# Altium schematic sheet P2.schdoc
size 297 x 210 mm; Symbol: Sheet-Symbol_A4; Company: 嘉立创EDA; Version: V1.0; Page Size: A4; @Project Name: MYNOVA-射频遥控; @Page Count: 2; @Update Date: 2025-11-18; @Create Date: 2025-11-18; @Schematic Name: 双频射频遥控V2; @Page No: 2; @Page Name: P2; Device: Sheet-Symbol_A4
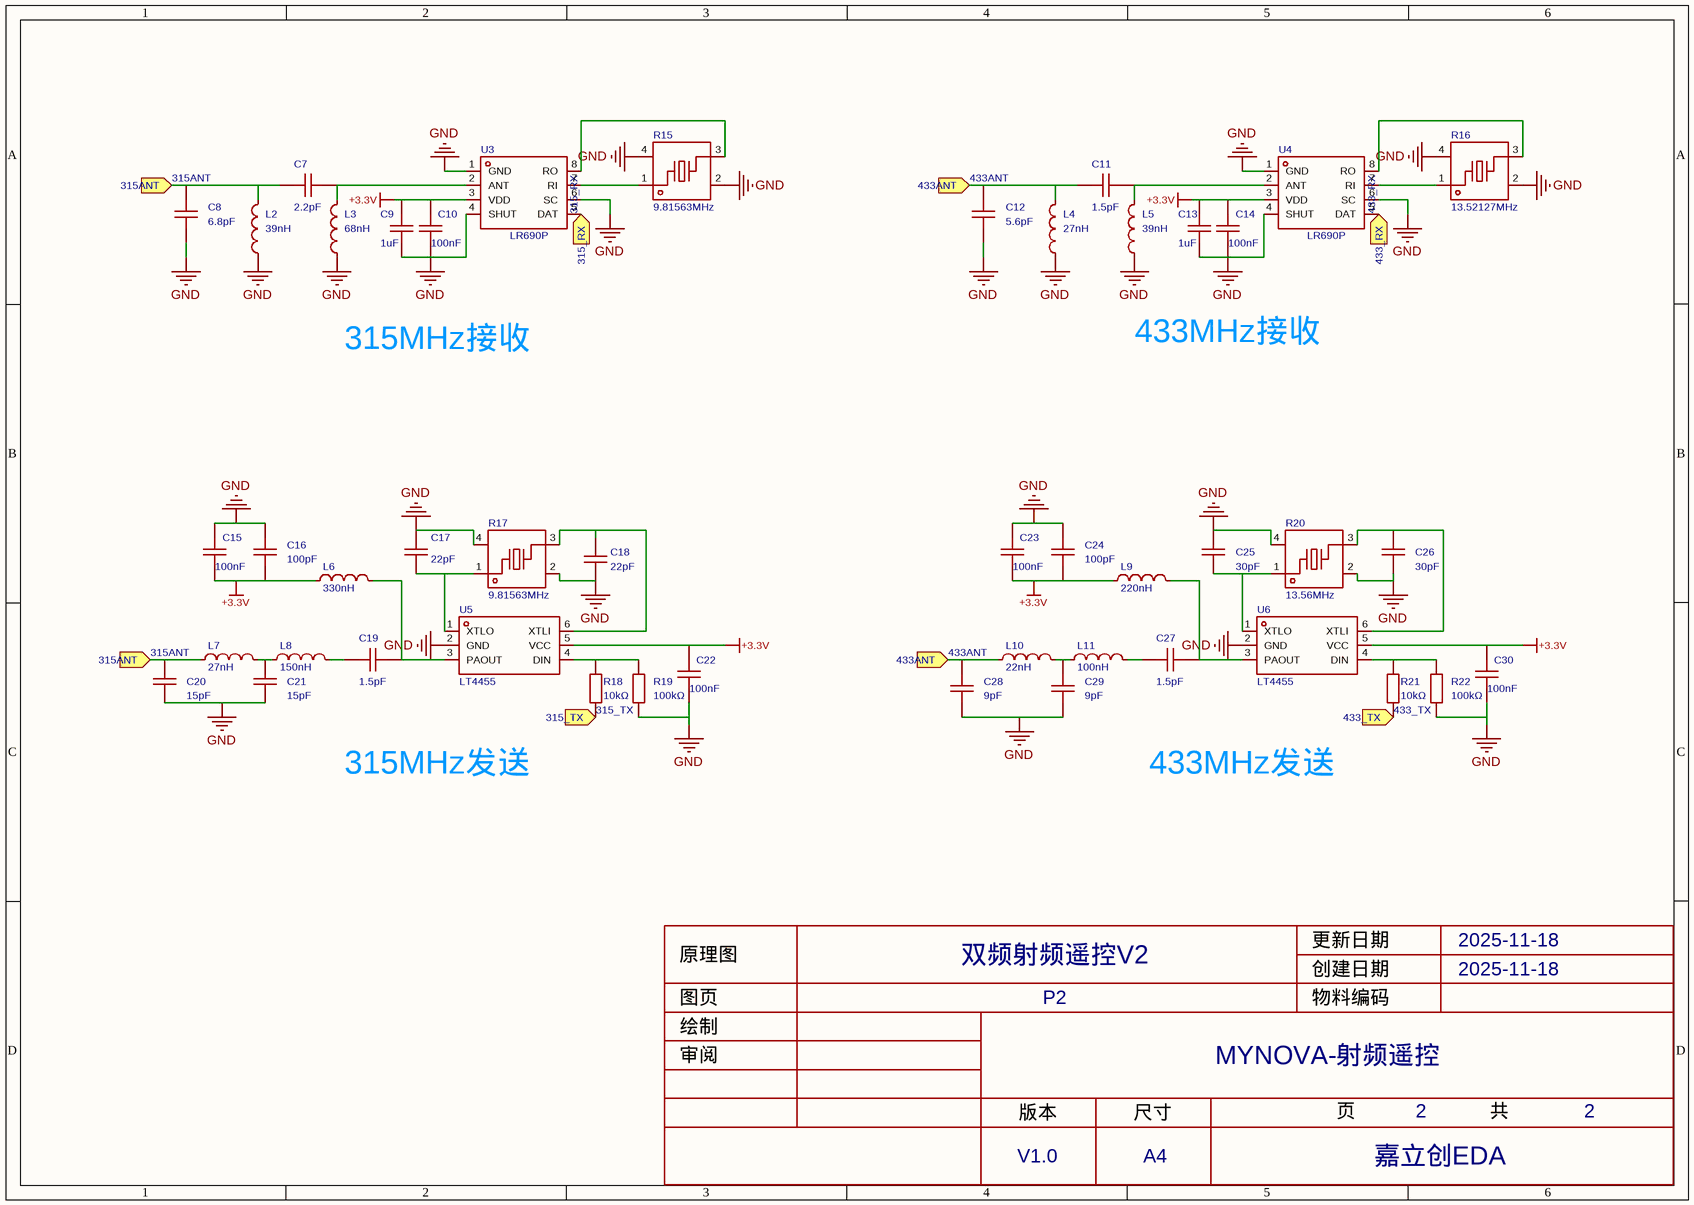
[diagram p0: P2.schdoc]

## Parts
C7  2.2pF  [C0603]
C8  6.8pF  [C0603]
C9  1uF  [C0603]
C10  100nF  [C0603]
C11  1.5pF  [C0603]
C12  5.6pF  [C0603]
C13  1uF  [C0603]
C14  100nF  [C0603]
C15  100nF  [C0603]
C16  100pF  [C0603]
C17  22pF  [C0603]
C18  22pF  [C0603]
C19  1.5pF  [C0603]
C20  15pF  [C0603]
C21  15pF  [C0603]
C22  100nF  [C0603]
C23  100nF  [C0603]
C24  100pF  [C0603]
C25  30pF  [C0603]
C26  30pF  [C0603]
C27  1.5pF  [C0603]
C28  9pF  [C0603]
C29  9pF  [C0603]
C30  100nF  [C0603]
L2  39nH  [L0603]
L3  68nH  [L0603]
L4  27nH  [L0603]
L5  39nH  [L0603]
L6  330nH  [L0603]
L7  27nH  [L0603]
L8  150nH  [IND-SMD_L1.8-W1.1]
L9  220nH  [L0603]
L10  22nH  [L0603]
L11  100nH  [L0603]
R15  9.81563MHz  [CRYSTAL-SMD_4P-L3.2-W2.5-BL]
R16  13.52127MHz  [CRYSTAL-SMD_4P-L3.2-W2.5-BL]
R17  9.81563MHz  [CRYSTAL-SMD_4P-L3.2-W2.5-BL]
R18  10kΩ  [R0603]
R19  100kΩ  [R0603]
R20  13.56MHz  [CRYSTAL-SMD_4P-L3.2-W2.5-BL_SIT8008BI]
R21  10kΩ  [R0603]
R22  100kΩ  [R0603]
U3  LR690P  [SOP-8_L4.9-W3.9-P1.27-LS6.0-BL]
U4  LR690P  [SOP-8_L4.9-W3.9-P1.27-LS6.0-BL]
U5  LT4455  [SOT-23-6_L2.9-W1.6-P0.95-LS2.8-BL]
U6  LT4455  [SOT-23-6_L2.9-W1.6-P0.95-LS2.8-BL]

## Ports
315_RX (in), 315_TX (in), 315ANT (in), 433_RX (in), 433_TX (in), 433ANT (in)

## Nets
+3.3V: C9.2 C10.2 C13.2 C14.2 C15.1 C16.1 C22.2 C23.1 C24.1 C30.2 L6.1 L9.1 U3.3(VDD) U4.3(VDD) U5.5(VCC) U6.5(VCC)
GND: C8.2 C9.1 C10.1 C12.2 C13.1 C14.1 C15.2 C16.2 C17.2 C18.1 C20.1 C21.1 C22.1 C23.2 C24.2 C25.2 C26.1 C28.2 C29.2 C30.1 L2.1 L3.1 L4.1 L5.1 R15.2(GND) R15.4(GND) R16.2(GND) R16.4(GND) R17.2(GND) R17.4(GND) R19.1 R20.2(GND) R20.4(GND) R22.1 U3.1(GND) U3.4(SHUT) U3.6(SC) U4.1(GND) U4.4(SHUT) U4.6(SC) U5.2(GND) U6.2(GND)
315_RX: U3.5(DAT) ; port 315_RX
315_TX: R18.2 ; port 315_TX
315ANT: C7.1 C8.1 C20.2 L2.2 L7.1 ; port 315ANT
433_RX: U4.5(DAT) ; port 433_RX
433_TX: R21.2 ; port 433_TX
433ANT: C11.2 C12.1 C28.1 L4.2 L10.1 ; port 433ANT
NetC7_2: C7.2 L3.2 U3.2(ANT)
NetC11_1: C11.1 L5.2 U4.2(ANT)
NetC17_1: C17.1 R17.1 U5.1(XTLO)
NetC18_2: C18.2 R17.3 U5.6(XTLI)
NetC19_1: C19.1 L6.2 U5.3(PAOUT)
NetC19_2: C19.2 L8.2
NetC21_2: C21.2 L7.2 L8.1
NetC25_1: C25.1 R20.1 U6.1(XTLO)
NetC26_2: C26.2 R20.3 U6.6(XTLI)
NetC27_1: C27.1 L9.2 U6.3(PAOUT)
NetC27_2: C27.2 L11.2
NetC29_1: C29.1 L10.2 L11.1
NetR15_1: R15.1 U3.7(RI)
NetR15_3: R15.3 U3.8(RO)
NetR16_1: R16.1 U4.7(RI)
NetR16_3: R16.3 U4.8(RO)
NetR18_1: R18.1 R19.2 U5.4(DIN)
NetR21_1: R21.1 R22.2 U6.4(DIN)

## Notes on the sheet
- 315MHz接收
- 433MHz接收
- 315MHz发送
- 433MHz发送

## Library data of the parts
C7 = CC0603CRNPO9BN2R2: 容值:2.2pF;额定电压:50V;温度系数:NP0;; Manufacturer: YAGEO(国巨); Add into BOM: yes; 3D Model: ac125912035d415993ca9572d50418b1; 3D Model Transform: 62.992,31.496,0,0,0,0,0,0,0; Temperature Coefficient: NP0; Voltage Rating: 50V; ModelName: C0603_L1.6-W0.8-H0.8
C8 = CC0603BRNPO9BN6R8: 容值:6.8pF;额定电压:50V;温度系数:NP0;; Manufacturer: YAGEO(国巨); Add into BOM: yes; 3D Model: ac125912035d415993ca9572d50418b1; 3D Model Transform: 62.992,31.496,0,0,0,0,0,0,0; Temperature Coefficient: NP0; Voltage Rating: 50V; ModelName: C0603_L1.6-W0.8-H0.8
C9 C13 = CC0603KRX5R8BB105: 容值:1uF;精度:±10%;额定电压:25V;材质(温度系数):X5R;; Manufacturer: YAGEO(国巨); Symbol: Capacitance; 3D Model: ac125912035d415993ca9572d50418b1; 3D Model Transform: 62.992,31.496,0,0,0,0,0,0,0; Tolerance: ±10%; Voltage Rated: 25V; Temperature Coefficient: X5R; AddInBom: yes; ModelName: C0603_L1.6-W0.8-H0.8
C10 C14 C15 C22 C23 C30 = CC0603KRX7R9BB104: 容值:100nF;精度:±10%;额定电压:50V;温度系数:X7R;; Manufacturer: YAGEO(国巨); Symbol: CC0603KRX7R9BB104_1; Add into BOM: yes; 3D Model: ac125912035d415993ca9572d50418b1; 3D Model Transform: 62.992,31.496,0,0,0,0,0,0,0; Tolerance: ±10%; Temperature Coefficient: X7R; Voltage Rating: 50V; ModelName: C0603_L1.6-W0.8-H0.8
C11 C19 C27 = CC0603BRNPO9BN1R5: 容值:1.5pF;额定电压:50V;材质(温度系数):NP0;; Manufacturer: YAGEO(国巨); Add into BOM: yes; 3D Model: ac125912035d415993ca9572d50418b1; 3D Model Transform: 62.992,31.496,0,0,0,0,0,0,0; Temperature Coefficient: NP0; Voltage Rated: 50V; ModelName: C0603_L1.6-W0.8-H0.8
C12 = CC0603BRNPO9BN5R6: 容值:5.6pF;额定电压:50V;温度系数:NP0;; Manufacturer: YAGEO(国巨); Add into BOM: yes; 3D Model: ac125912035d415993ca9572d50418b1; 3D Model Transform: 62.992,31.496,0,0,0,0,0,0,0; Temperature Coefficient: NP0; Voltage Rating: 50V; ModelName: C0603_L1.6-W0.8-H0.8
C16 C24 = CC0603JRNPO9BN101: 容值:100pF;精度:±5%;额定电压:50V;温度系数:NP0;; Manufacturer: YAGEO(国巨); Add into BOM: yes; 3D Model: ac125912035d415993ca9572d50418b1; 3D Model Transform: 62.992,31.496,0,0,0,0,0,0,0; Temperature Coefficient: NP0; Voltage Rating: 50V; Tolerance: ±5%; ModelName: C0603_L1.6-W0.8-H0.8
C17 C18 = CC0603JRNPO9BN220: 容值:22pF;精度:±5%;额定电压:50V;温度系数:NP0;; Manufacturer: YAGEO(国巨); Add into BOM: yes; 3D Model: ac125912035d415993ca9572d50418b1; 3D Model Transform: 62.992,31.496,0,0,0,0,0,0,0; Temperature Coefficient: NP0; Voltage Rating: 50V; Tolerance: ±5%; ModelName: C0603_L1.6-W0.8-H0.8
C20 C21 = CC0603JRNPO9BN150: 容值:15pF;精度:±5%;额定电压:50V;温度系数:NP0;; Manufacturer: YAGEO(国巨); Add into BOM: yes; 3D Model: ac125912035d415993ca9572d50418b1; 3D Model Transform: 62.992,31.496,0,0,0,0,0,0,0; Temperature Coefficient: NP0; Voltage Rating: 50V; Tolerance: ±5%; ModelName: C0603_L1.6-W0.8-H0.8
C25 C26 = CC0603JRNPO9BN300: 容值:30pF;精度:±5%;额定电压:50V;温度系数:NP0;; Manufacturer: YAGEO(国巨); Add into BOM: yes; 3D Model: ac125912035d415993ca9572d50418b1; 3D Model Transform: 62.992,31.496,0,0,0,0,0,0,0; Temperature Coefficient: NP0; Voltage Rating: 50V; Tolerance: ±5%; ModelName: C0603_L1.6-W0.8-H0.8
C28 C29 = CC0603CRNPO9BN9R0: 容值:9pF;额定电压:50V;材质(温度系数):NP0;; Manufacturer: YAGEO(国巨); Add into BOM: yes; 3D Model: ac125912035d415993ca9572d50418b1; 3D Model Transform: 62.992,31.496,0,0,0,0,0,0,0; Temperature Coefficient: NP0; Voltage Rated: 50V; ModelName: C0603_L1.6-W0.8-H0.8
L2 L5 = VHF160808H39NJT: 电感值:39nH;精度:±5%;额定电流:300mA;饱和电流(Isat):-;直流电阻(DCR):1Ω;; Manufacturer: FH(风华); Add into BOM: yes; 3D Model: 2bc5ec593d464d6ba9807aec0b5673c2; 3D Model Transform: 62.992,31.496,0,180,0,0,0.094,0.629,0; Tolerance: ±5%; Current Rating: 300mA; DC Resistance(DCR): 1Ω; ModelName: L0603_L1.6-W0.8-H0.5_BEAD
L3 = VHF160808H68NJT: 电感值:68nH;精度:±5%;额定电流:200mA;饱和电流(Isat):-;直流电阻(DCR):1Ω;; Manufacturer: FH(风华); Add into BOM: yes; 3D Model: 2bc5ec593d464d6ba9807aec0b5673c2; 3D Model Transform: 62.992,31.496,0,180,0,0,0.094,0.629,0; Tolerance: ±5%; Rated Current: 200mA; DC Resistance (DCR): 1Ω; ModelName: L0603_L1.6-W0.8-H0.5_BEAD
L4 L7 = VHF160808H27NJT: 电感值:27nH;精度:±5%;额定电流:300mA;饱和电流(Isat):-;直流电阻(DCR):800mΩ;; Manufacturer: FH(风华); Add into BOM: yes; 3D Model: 2bc5ec593d464d6ba9807aec0b5673c2; 3D Model Transform: 62.992,31.496,0,180,0,0,0.094,0.629,0; Tolerance: ±5%; Rated Current: 300mA; DC Resistance (DCR): 800mΩ; ModelName: L0603_L1.6-W0.8-H0.5_BEAD
L6 = SCC1608CR33JSP: 电感值:330nH;精度:±5%;额定电流:150mA;饱和电流(Isat):-;直流电阻(DCR):2.8Ω;; Manufacturer: Sunltech(顺磁); Add into BOM: yes; 3D Model: 2bc5ec593d464d6ba9807aec0b5673c2; 3D Model Transform: 62.992,31.496,0,180,0,0,0.094,0.629,0; Tolerance: ±5%; Current Rating: 150mA; DC Resistance(DCR): 2.8Ω; ModelName: L0603_L1.6-W0.8-H0.5_BEAD
L8 = FHW0603UCR15JST: 电感值:150nH;精度:±5%;额定电流:280mA;饱和电流(Isat):-;直流电阻(DCR):800mΩ;; Manufacturer: FH(风华); Add into BOM: yes; 3D Model: cfc0ddda825b43ad9376d60a3a37fd7f; 3D Model Transform: 70.866,43.307,0,0,0,0,0,0,0; Tolerance: ±5%; Rated Current: 280mA; DC Resistance (DCR): 800mΩ; Q @ Freq: 28@150MHz; Frequency - Self Resonant: 990MHz; ModelName: IND-SMD_L1.8-W1.1-H1.0
L9 = VHF160808HR22JT: 电感值:220nH;精度:±5%;额定电流:200mA;饱和电流(Isat):-;直流电阻(DCR):2.4Ω;; Manufacturer: FH(风华); Add into BOM: yes; 3D Model: 2bc5ec593d464d6ba9807aec0b5673c2; 3D Model Transform: 62.992,31.496,0,180,0,0,0.094,0.629,0; Tolerance: ±5%; Rated Current: 200mA; DC Resistance (DCR): 2.4Ω; ModelName: L0603_L1.6-W0.8-H0.5_BEAD
L10 = VHF160808H22NJT: 电感值:22nH;精度:±5%;额定电流:300mA;饱和电流(Isat):-;直流电阻(DCR):600mΩ;; Manufacturer: FH(风华); Add into BOM: yes; 3D Model: 2bc5ec593d464d6ba9807aec0b5673c2; 3D Model Transform: 62.992,31.496,0,180,0,0,0.094,0.629,0; Tolerance: ±5%; Current Rating: 300mA; DC Resistance(DCR): 600mΩ; ModelName: L0603_L1.6-W0.8-H0.5_BEAD
L11 = SDCL1608CR10JTDF: 电感值:100nH;精度:±5%;额定电流:300mA;饱和电流(Isat):-;直流电阻(DCR):1.2Ω;; Manufacturer: Sunlord(顺络); Add into BOM: yes; 3D Model: 2bc5ec593d464d6ba9807aec0b5673c2; 3D Model Transform: 62.992,31.496,0,180,0,0,0.094,0.629,0; Tolerance: ±5%; Rated Current: 300mA; Frequency - Self Resonant: 700MHz; DC Resistance(DCR): 1.2Ω; Q @ Frequency: 8@100MHz; ModelName: L0603_L1.6-W0.8-H0.5_BEAD
R15 R17 = 3TJ498156JYLBC: Manufacturer: JYJE(晶友嘉); Add into BOM: yes; 3D Model: 02485e56ba8d4732a26526d2983fc729; 3D Model Transform: 125.984,98.425,0,0,0,0,0,0,0
R16 = TAXM13.52127M4RLBDDT2T: 晶振类型:贴片晶振;频率:13.52127MHz;常温频差:±10ppm;负载电容:20pF;频率稳定度:±20ppm;; Manufacturer: YJX(雅晶鑫); Add into BOM: yes; 3D Model: 02485e56ba8d4732a26526d2983fc729; 3D Model Transform: 125.984,98.425,0,0,0,0,0,0,0; Normal temperature Frequency Tolerance: ±10ppm; Load Capacitance: 20pF; Frequency Stability: ±20ppm; Equivalent Series Resistance(ESR): 55Ω
R18 R21 = 0603WAF1002T5E: 电阻类型:厚膜电阻;阻值:10kΩ;精度:±1%;功率:100mW;最大工作电压:75V;温度系数:±100ppm/℃;; Manufacturer: UNI-ROYAL(厚声); Symbol: RC0603FR-071KL; Add into BOM: yes; 3D Model: fc143cca1e79419f9cd78b61e9279f08; 3D Model Transform: 31.8897,63.7794,0,90,0,0,0,0,0; Tolerance: ±1%; Power(Watts): 100mW; Overload Voltage (Max): 75V
R19 R22 = 0603WAF1003T5E: 电阻类型:厚膜电阻;阻值:100kΩ;精度:±1%;功率:100mW;工作电压:75V;温度系数:±100ppm/℃;; Manufacturer: UNI-ROYAL(厚声); Add into BOM: yes; 3D Model: fc143cca1e79419f9cd78b61e9279f08; 3D Model Transform: 31.8897,63.7794,0,90,0,0,0,0,0; Tolerance: ±1%; Power(Watts): 100mW; Voltage-Supply(Max): 75V
R20 = XL2EL89CSI-111YLC-13.56M: 晶振类型:贴片晶振;频率:13.56MHz;常温频差:±10ppm;负载电容:20pF;频率稳定度:±20ppm;; Manufacturer: YXC(扬兴晶振); Add into BOM: yes; 3D Model: 86cd4e9b22d34351aea1c0646460e097; 3D Model Transform: 125.984,98.425,0,0,0,0,0,0,0; Normal temperature Frequency Tolerance: ±10ppm; Load Capacitance: 20pF; Frequency Stability: ±20ppm
U3 U4 = LR690P: 频率范围:300MHz~440MHz;数据速率:19Kbps;灵敏度:-116dBm;典型应用频率:433.92MHz;; Manufacturer: 蜂鸟无线; Add into BOM: yes; 3D Model: 75c24a7891ee4dd6bdac16a7163ff87e; 3D Model Transform: 192.913,236.22,0,0,0,0,0,0,0; Voltage - Supply: 2V~5.5V; Data Rate: 19Kbps; ModelName: SOP-8_L4.9-W3.9-P1.27-LS6.0-BL-1
U5 U6 = LT4455: 频率范围:315MHz~433.92MHz;; Manufacturer: 蜂鸟无线; Add into BOM: yes; 3D Model: 18da8f6c14a34920b3e136b5c401a119; 3D Model Transform: 110.236,113.364,0,90,0,0,0.0005,0.0005,0; Voltage - Supply: 2V~5V; Output Power: 12dBm; Current Of Transmitting: 10mA; ModelName: SOT-23-6_L2.9-W1.6-H1.5-LS2.8-P0.95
